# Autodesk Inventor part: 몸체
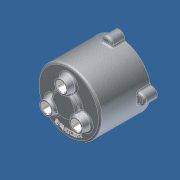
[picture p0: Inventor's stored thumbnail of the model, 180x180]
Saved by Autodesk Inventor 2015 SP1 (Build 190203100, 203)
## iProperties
Created: 2012-05
Part Number: 몸체
Document SubType Name: 모델링
Designer: SeoGD™
Material: 일반
Appearance: 기본값
Mass: 175.481 g
Surface Area: 687.661 cm^2
Volume: 175.481 cm^3
Density: 1 g/cm^3
변환 표준: STEP AP214IS
파일 이름: C:\Users\SeoGD\Desktop\?쒗뿕\紐몄껜.stp
전처리기: Build: 253, Release: 2010 SP1 - Date: Wed 07/29/2009
전송 단위: 밀리미터
불확실성: 0.01
Author: SeoGD™
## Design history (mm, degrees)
sketch "스케치2"
  geometry: C1 r 50 at (0, 0); 1 further point
  constraints: 1 centre point, 1 coincident
  dimensions: "d9" = 100 diameter of C1
extrude "돌출2" new body sketch "스케치2" distance "d10" = 80; taper "d11" = 0 deg
feature "쉘1" dims "d12" = 5
sketch "스케치3" dims "d13" = 55
  geometry: C1 r 7.5 at (0, 27.5); C2 r 12.5 at (0, 27.5); 2 further points
  constraints: 2 centre point, 2 coincident, 2 vertical alignment, 2 other
  dimensions: "d14" = 15 diameter of C1; "d15" = 25 diameter of C2
extrude "돌출3" join sketch "스케치3" distance "d16" = 12; taper "d17" = -10 deg
hole "구멍2" diameter "d20" = 15; stored, may be unused: countersink angle "d24" = 90 deg, drill point angle "d26" = 118 deg; dims "d18" = 10, "d19" = 10, "d21" = 6, "d22" = 4, "d23" = 2, "d25" = 15
chamfer "모따기1" distance "d27" = 1; stored, may be unused: second distance "d28" = 2, angle "d29" = 45 deg
sketch "스케치4"
  geometry: L1 (0, 0)-(0, 88); L2 (0, 70)-(13.16, 70); L3 (-45, 75)-(45, 75) reference; L4 (-50, 80)-(50, 80) reference; L5 (13.16, 70)-(14.5, 75); L6 (20, 80)-(20, 88); L7 (20, 88)-(0, 88); L8 (20, 80)-(14.5, 75)
  constraints: 12 end point, 3 point on line, 2 perpendicular, 1 vertical
  dimensions: "d34" = 40 diameter of L6 L1; "d35" = 105 deg angle of L5 L3; "d36" = 5 distance between parallel lines of L2 L3; "d37" = 8 distance between parallel lines of L7 L4; "d51" = 29 diameter of L5.end L1
revolve "회전1" sketch "스케치4" stored, may be unused: angle "d38" = 90 deg
hole "구멍3" diameter "d41" = 15; stored, may be unused: countersink angle "d45" = 90 deg, drill point angle "d47" = 0 deg; dims "d39" = 10, "d40" = 10, "d42" = 6, "d43" = 22, "d44" = 13, "d46" = 15
chamfer "모따기2" distance "d48" = 1; stored, may be unused: second distance "d49" = 2, angle "d50" = 45 deg
fillet "모깎기1" dims "d52" = 3
fillet "모깎기2" dims "d53" = 3, "d72" = 0.2
sketch "스케치5"
  geometry: A1 r 50 centre (0, 0) between (50, 0) and (-8.074, 49.344) reference; A2 r 8.5 centre (0, 52) between (8.074, 49.344) and (-8.074, 49.344); 1 further point
  constraints: 5 point on circle, 1 centre point, 1 horizontal alignment
  dimensions: "d54" = 90 deg dimension on point (0, 0) A2.centre A1.start; "d55" = 52 distance of A2.centre point (0, 0); "d56" = 17 diameter of A2
extrude "돌출4" join sketch "스케치5" distance "d57" = 20; taper "d58" = 0 deg
fillet "모깎기3" dims "d59" = 3
hole "구멍4" diameter "d62" = 4.134; stored, may be unused: countersink angle "d66" = 90 deg, drill point angle "d68" = 118 deg; dims "d60" = 10, "d61" = 10, "d63" = 12, "d64" = 22, "d65" = 13, "d67" = 15
sketch "스케치6"
  geometry: C1 r 47 at (0, 0) reference; C2 r 42.5 at (0, 0); 1 further point
  constraints: 1 centre point, 1 coincident, 1 other
  dimensions: "d73" = 85 diameter of C2
feature "엠보싱1" sketch "스케치6" dims "d74" = 1, "d75" = 0
node "솔리드1"
node "솔리드 본체"
node "곡면 본체"
pattern_circular "원형 패턴1" dims "d31" = 360 deg
pattern_circular "원형 패턴2" dims "d70" = 360 deg
node "솔리드2"
